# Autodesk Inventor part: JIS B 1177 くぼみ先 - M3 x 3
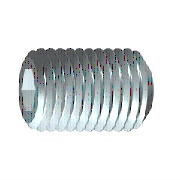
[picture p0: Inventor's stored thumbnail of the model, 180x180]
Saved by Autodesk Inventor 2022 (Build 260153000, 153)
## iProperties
Created: 2021-02
Part Number: JIS B 1177 くぼみ先 - M3 x 3
Material: 鋼、軟鋼
Description: 六角穴付き止めねじ - くぼみ先
Document SubType Name: Modeling
Standard: JIS B 1177 くぼみ先
Designer: shimizu
Standards Organization: JIS
Language: ja-JP
Size Designation: M3 x 3
Categories: <MemberInstance><Categories><Category DisplayName="締結器具" InternalName="e4da775c-781d-43d5-af7c-5136215cf5a6" Mnemonic="FSTN"><Category DisplayName="ボルト" Interna
Density: 7.85 g/cm^3
Appearance: 半つや出し
IsCustomPart: 0
Author: shimizu
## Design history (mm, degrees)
sketch "スケッチ1"
  geometry: L1 (0.421, 0)-(1.3, 0); L2 (3, 0.866)-(3, 1.5); L3 (3, 1.5)-(0, 1.5); L4 (3, 0.866)-(1.8, 0.866); L5 (1.8, 0.866)-(1.3, 0); L6 (0, 0.7)-(0.421, 0); L7 (0, -0.3)-(0, 1.8) reference; L8 (0, 0.7)-(0, 1.5); 1 further point
  constraints: 14 end point, 2 parallel, 2 perpendicular, 2 point on line, 1 horizontal
  dimensions: "d0" = 1.2 distance of L2.start L4.end (= INTI); "d1" = 60 deg angle of L5 L1; "d2" = 3 diameter of L3 L1 (= NND); "d3" = 1.73205 diameter of L4 L1 (= 1.1547 x SW); "d4" = 3 distance from line of L2 L6.start (= NLG); "d5" = 59 deg angle of L1 L6 (= 0.5 x ANG); "d7" = 1.4 diameter of L6.start L1 (= SPD)
revolve "ボディ" sketch "スケッチ1" stored, may be unused: angle "d6" = 90 deg
sketch "スケッチ2"
  geometry: L1 (0.866, 0)-(0.433, -0.75); L2 (0.433, -0.75)-(-0.433, -0.75); L3 (-0.433, -0.75)-(-0.866, 0); L4 (-0.866, 0)-(-0.433, 0.75); L5 (-0.433, 0.75)-(0.433, 0.75); L6 (0.433, 0.75)-(0.866, 0); C1 r 1.5 at (0, 0) reference; A1 r 0.866 centre (0, 0) between (0.866, 0) and (0.433, -0.75) reference; 1 further point
  constraints: 12 end point, 2 point on circle, 1 coincident, 1 horizontal, 11 other
extrude "長穴" join sketch "スケッチ2" distance "d8" = 1.2 (= INTI); taper "d9" = 0 deg
workaxis "Work Axis1"
workplane "Work Plane1"
body "Solid1"
chamfer "面取り1" distance "d10" = 0.8 (= -0.5 x SPD + 0.5 x NND); stored, may be unused: angle "d11" = 60 deg (= FAWI), second distance "d33" = 0.8 (= -0.5 x SPD + 0.5 x NND)
feature "ねじ" dims "d14" = 3 (= NLG), "d15" = 0
chamfer "面取り2" distance "d12" = 0.30673 (= -0.5 x GD1 + 0.5 x NND); stored, may be unused: angle "d13" = 60 deg (= FAWI), second distance "d34" = 0.30673 (= -0.5 x GD1 + 0.5 x NND)
other parameters: "NND" = 3 [user parameter; used in 5 equation terms], "NLG" = 3 [user parameter; used in 2 equation terms], "INTI" = 1.2 [user parameter; used in 2 equation terms], "FAWI" = 60 deg [user parameter; used in 2 equation terms], "SW" = 1.5 [user parameter; used in 2 equation terms], "GD1" = 2.38655 (= THREADDIA - 1.2269 x PTC) [user parameter; used in 2 equation terms], "ANG" = 118 deg [user parameter; used in 1 equation term], "FAWI1" = 45 deg [user parameter], "SPD" = 1.4 [user parameter; used in 3 equation terms], "d16" = 0, "d35" = 0, "d37" = 0, "GUL" = 0.30673 (= 0.61345 x PTC) [user parameter], "TOA" = 30 deg [user parameter], "THREADDIA" = 3 [user parameter; used in 1 equation term], "PTC" = 0.5 [user parameter; used in 4 equation terms], "GAL" = 0.30673 (= 0.61345 x PTC) [user parameter], "E0" = 1.7325 (= 1.155 x SW) [user parameter]
